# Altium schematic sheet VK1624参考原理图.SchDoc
size A3
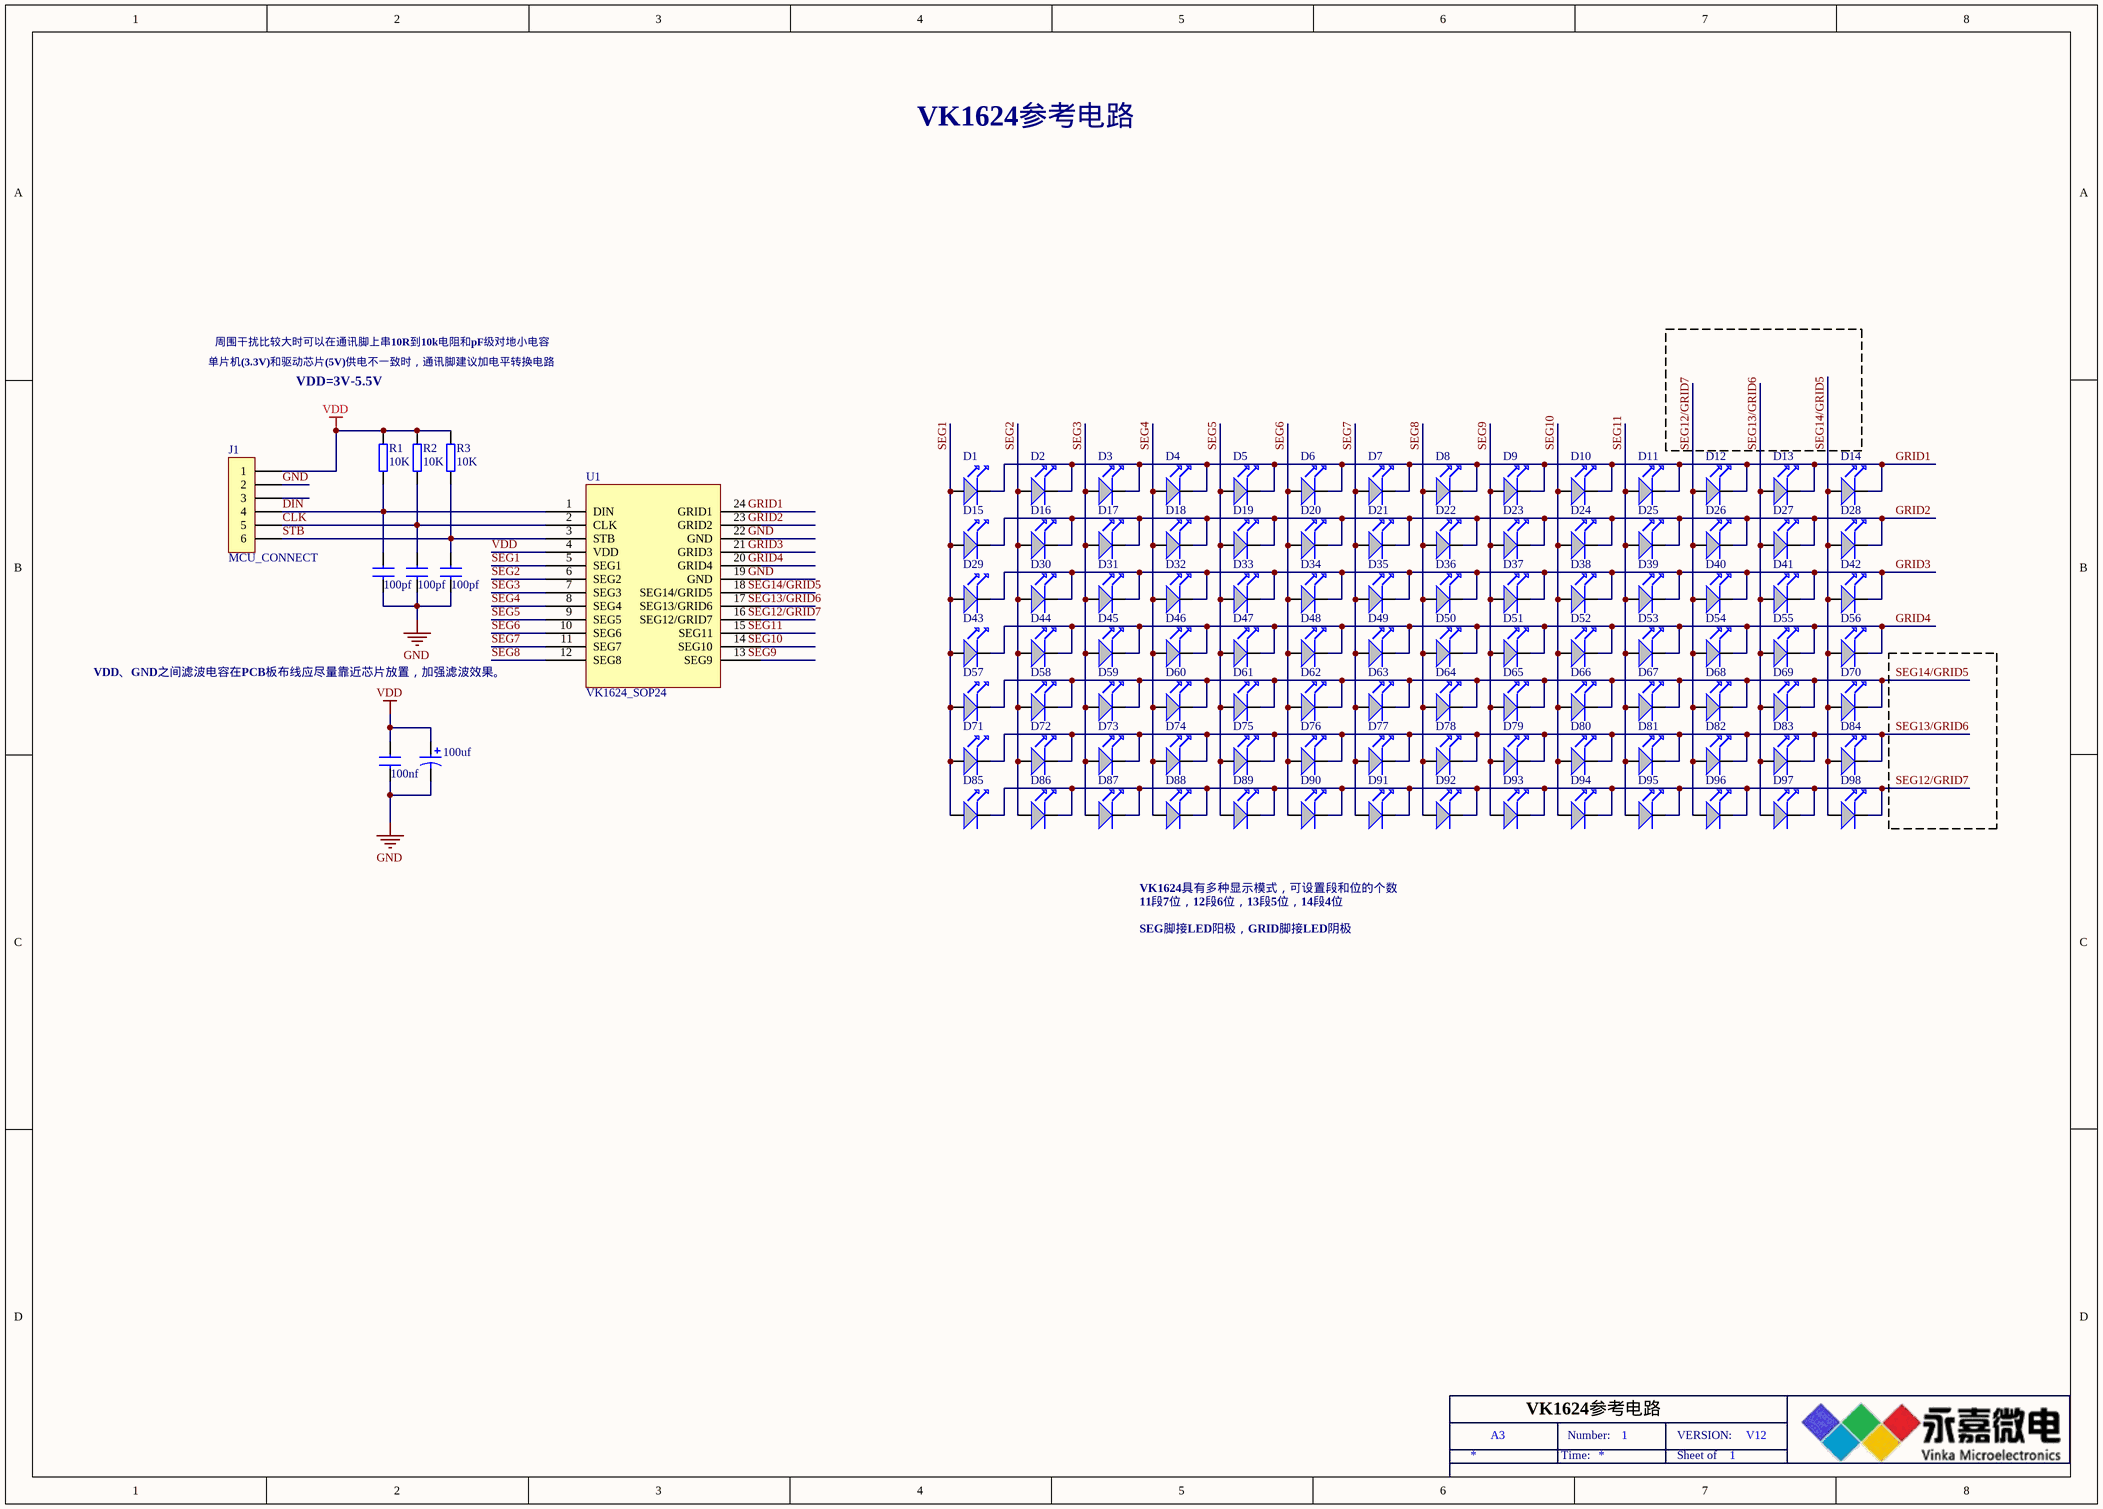
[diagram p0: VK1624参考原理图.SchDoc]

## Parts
100nf  CAP  (value not drawn)
100nf1  100pf
100nf2  100pf
100nf3  100pf
100uf  CAP2  (value not drawn)
D1  (no value)  [1206-LED]
D2  (no value)  [1206-LED]
D3  (no value)  [1206-LED]
D4  (no value)  [1206-LED]
D5  (no value)  [1206-LED]
D6  (no value)  [1206-LED]
D7  (no value)  [1206-LED]
D8  (no value)  [1206-LED]
D9  (no value)  [1206-LED]
D10  (no value)  [1206-LED]
D11  (no value)  [1206-LED]
D12  (no value)  [1206-LED]
D13  (no value)  [1206-LED]
D14  (no value)  [1206-LED]
D15  (no value)  [1206-LED]
D16  (no value)  [1206-LED]
D17  (no value)  [1206-LED]
D18  (no value)  [1206-LED]
D19  (no value)  [1206-LED]
D20  (no value)  [1206-LED]
D21  (no value)  [1206-LED]
D22  (no value)  [1206-LED]
D23  (no value)  [1206-LED]
D24  (no value)  [1206-LED]
D25  (no value)  [1206-LED]
D26  (no value)  [1206-LED]
D27  (no value)  [1206-LED]
D28  (no value)  [1206-LED]
D29  (no value)  [1206-LED]
D30  (no value)  [1206-LED]
D31  (no value)  [1206-LED]
D32  (no value)  [1206-LED]
D33  (no value)  [1206-LED]
D34  (no value)  [1206-LED]
D35  (no value)  [1206-LED]
D36  (no value)  [1206-LED]
D37  (no value)  [1206-LED]
D38  (no value)  [1206-LED]
D39  (no value)  [1206-LED]
D40  (no value)  [1206-LED]
D41  (no value)  [1206-LED]
D42  (no value)  [1206-LED]
D43  (no value)  [1206-LED]
D44  (no value)  [1206-LED]
D45  (no value)  [1206-LED]
D46  (no value)  [1206-LED]
D47  (no value)  [1206-LED]
D48  (no value)  [1206-LED]
D49  (no value)  [1206-LED]
D50  (no value)  [1206-LED]
D51  (no value)  [1206-LED]
D52  (no value)  [1206-LED]
D53  (no value)  [1206-LED]
D54  (no value)  [1206-LED]
D55  (no value)  [1206-LED]
D56  (no value)  [1206-LED]
D57  (no value)  [1206-LED]
D58  (no value)  [1206-LED]
D59  (no value)  [1206-LED]
D60  (no value)  [1206-LED]
D61  (no value)  [1206-LED]
D62  (no value)  [1206-LED]
D63  (no value)  [1206-LED]
D64  (no value)  [1206-LED]
D65  (no value)  [1206-LED]
D66  (no value)  [1206-LED]
D67  (no value)  [1206-LED]
D68  (no value)  [1206-LED]
D69  (no value)  [1206-LED]
D70  (no value)  [1206-LED]
D71  (no value)  [1206-LED]
D72  (no value)  [1206-LED]
D73  (no value)  [1206-LED]
D74  (no value)  [1206-LED]
D75  (no value)  [1206-LED]
D76  (no value)  [1206-LED]
D77  (no value)  [1206-LED]
D78  (no value)  [1206-LED]
D79  (no value)  [1206-LED]
D80  (no value)  [1206-LED]
D81  (no value)  [1206-LED]
D82  (no value)  [1206-LED]
D83  (no value)  [1206-LED]
D84  (no value)  [1206-LED]
D85  (no value)  [1206-LED]
D86  (no value)  [1206-LED]
D87  (no value)  [1206-LED]
D88  (no value)  [1206-LED]
D89  (no value)  [1206-LED]
D90  (no value)  [1206-LED]
D91  (no value)  [1206-LED]
D92  (no value)  [1206-LED]
D93  (no value)  [1206-LED]
D94  (no value)  [1206-LED]
D95  (no value)  [1206-LED]
D96  (no value)  [1206-LED]
D97  (no value)  [1206-LED]
D98  (no value)  [1206-LED]
J1  MCU_CONNECT
R1  10K  [0603-R]
R2  10K  [0603-R]
R3  10K  [0603-R]
U1  VK1624_SOP24

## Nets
GND: 100nf.2 100nf1.2 100nf2.2 100nf3.2 100uf.2 J1.2
VDD: 100nf.1 100uf.1 J1.1 R1.1 R2.1 R3.1 U1.4(VDD)
CLK: 100nf2.1 J1.5 R2.2 U1.2(CLK)
DIN: 100nf1.1 J1.4 R1.2 U1.1(DIN)
GRID1: D1.2 D2.2 D3.2 D4.2 D5.2 D6.2 D7.2 D8.2 D9.2 D10.2 D11.2 D12.2 D13.2 D14.2
GRID2: D15.2 D16.2 D17.2 D18.2 D19.2 D20.2 D21.2 D22.2 D23.2 D24.2 D25.2 D26.2 D27.2 D28.2
GRID3: D29.2 D30.2 D31.2 D32.2 D33.2 D34.2 D35.2 D36.2 D37.2 D38.2 D39.2 D40.2 D41.2 D42.2
GRID4: D43.2 D44.2 D45.2 D46.2 D47.2 D48.2 D49.2 D50.2 D51.2 D52.2 D53.2 D54.2 D55.2 D56.2
SEG1: D1.1 D15.1 D29.1 D43.1 D57.1 D71.1 D85.1 U1.5(SEG1)
SEG2: D2.1 D16.1 D30.1 D44.1 D58.1 D72.1 D86.1 U1.6(SEG2)
SEG3: D3.1 D17.1 D31.1 D45.1 D59.1 D73.1 D87.1 U1.7(SEG3)
SEG4: D4.1 D18.1 D32.1 D46.1 D60.1 D74.1 D88.1 U1.8(SEG4)
SEG5: D5.1 D19.1 D33.1 D47.1 D61.1 D75.1 D89.1 U1.9(SEG5)
SEG6: D6.1 D20.1 D34.1 D48.1 D62.1 D76.1 D90.1 U1.10(SEG6)
SEG7: D7.1 D21.1 D35.1 D49.1 D63.1 D77.1 D91.1 U1.11(SEG7)
SEG8: D8.1 D22.1 D36.1 D50.1 D64.1 D78.1 D92.1 U1.12(SEG8)
SEG9: D9.1 D23.1 D37.1 D51.1 D65.1 D79.1 D93.1
SEG10: D10.1 D24.1 D38.1 D52.1 D66.1 D80.1 D94.1
SEG11: D11.1 D25.1 D39.1 D53.1 D67.1 D81.1 D95.1
SEG12/GRID7: D12.1 D26.1 D40.1 D54.1 D68.1 D82.1 D85.2 D86.2 D87.2 D88.2 D89.2 D90.2 D91.2 D92.2 D93.2 D94.2 D95.2 D96.1 D96.2 D97.2 D98.2
SEG13/GRID6: D13.1 D27.1 D41.1 D55.1 D69.1 D71.2 D72.2 D73.2 D74.2 D75.2 D76.2 D77.2 D78.2 D79.2 D80.2 D81.2 D82.2 D83.1 D83.2 D84.2 D97.1
SEG14/GRID5: D14.1 D28.1 D42.1 D56.1 D57.2 D58.2 D59.2 D60.2 D61.2 D62.2 D63.2 D64.2 D65.2 D66.2 D67.2 D68.2 D69.2 D70.1 D70.2 D84.1 D98.1
STB: 100nf3.1 J1.6 R3.2 U1.3(STB)

Not connected (* = marked no-connect by the designer): J1 3; U1 13(SEG9) 14(SEG10) 15(SEG11) 16(SEG12/GRID7) 17(SEG13/GRID6) 18(SEG14/GRID5) 19(GND) 20(GRID4) 21(GRID3) 22(GND) 23(GRID2) 24(GRID1)

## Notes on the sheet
- VK1624参考电路
- 单片机(3.3V)和驱动芯片(5V)供电不一致时，通讯脚建议加电平转换电路
- 周围干扰比较大时可以在通讯脚上串10R到10k电阻和pF级对地小电容
- VDD=3V-5.5V
- VDD、GND之间滤波电容在PCB板布线应尽量靠近芯片放置，加强滤波效果。
- VK1624具有多种显示模式，可设置段和位的个数
- 11段7位，12段6位，13段5位，14段4位
- SEG脚接LED阳极，GRID脚接LED阴极
- A3
- Time:
- Number:
- 1
- Sheet of
- VERSION:
- V12
- Labels drawn without touching a wire or pin: GND, GRID1, GRID2, GRID3, GRID4, SEG9, SEG10, SEG11, SEG12/GRID7, SEG13/GRID6, SEG14/GRID5

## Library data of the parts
100nf 100nf1-100nf3 = CAP: Capacitor
100uf = CAP2: Bi-Polar Capacitor
D1-D98 = LED: Text Field1: 30; Text Field2: 20
J1 = CON6: Connector
R1-R3 = RES: Resistor
U1 = VK1624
